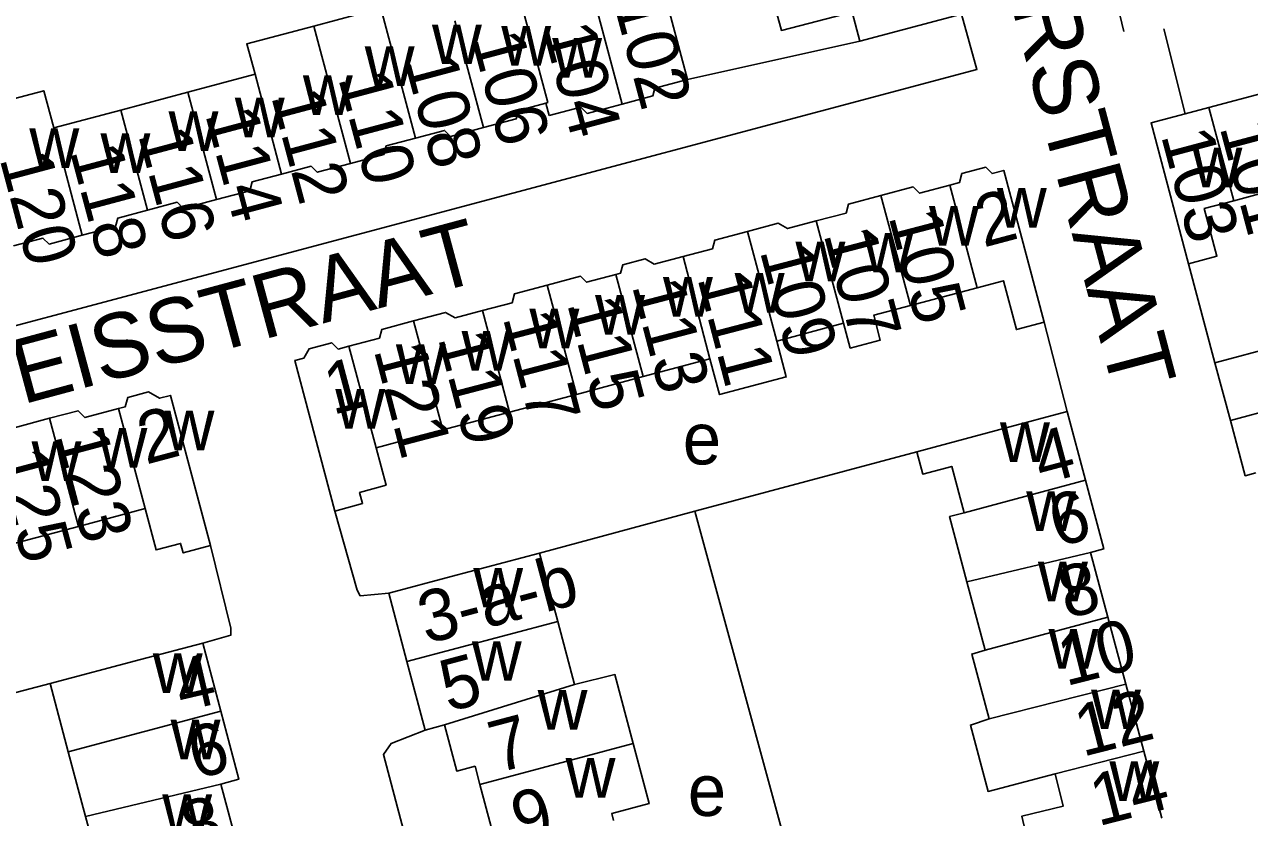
# Model space of a CAD drawing. Extents: x 161258 to 163262, y 380749 to 382054.
# Drawn here: x 162725.4 to 162820.5, y 381008.4 to 381069.9 of the extents above; entities that cross this region are included whole.
import ezdxf

# ---------------------------------------------------------------- set-up
doc = ezdxf.new("R2010")
doc.units = 0
for name, color, linetype in [('BLT_Basislijn', 7, 'Continuous'), ('BLT_Bebouwing', 7, 'Continuous'), ('BLT_Centroide', 7, 'Continuous'), ('BLT_Huisnummer', 7, 'Continuous'), ('BLT_Huisnummer_ tussenligend', 7, 'Continuous'), ('BLT_Huisnummer_reeks', 7, 'Continuous'), ('BLT_Onderverdeling_panden', 7, 'Continuous'), ('BLT_Straatnaam', 7, 'Continuous')]:
    doc.layers.add(name, color=color, linetype=linetype)

msp = doc.modelspace()

# ---------------------------------------------------------------- linework, layer by layer
at = {"layer": 'BLT_Basislijn'}
for p, q in [((162810.726, 381069.348), (162809.642, 381073.81)), ((162813.831, 381069.574), (162815.478, 381062.977)), ((162776.867, 381065.641), (162790.25, 381068.607)), ((162815.742, 381051.349), (162817.787, 381043.662)), ((162804.535, 381046.81), (162806.315, 381039.883)), ((162777.445, 381032.148), (162794.663, 381036.768)), ((162765.392, 381028.911), (162777.445, 381032.148)), ((162727.427, 381018.777), (162713.306, 381015.167))]:
    msp.add_line(p, q, dxfattribs=at)
for points in [[(162606.783, 381015.115), (162799.33, 381066.419), (162798.133, 381070.7)], [(162753.691, 381025.795), (162751.479, 381025.578), (162751.237, 381026.024), (162749.506, 381032.166)], [(162788.928, 380990.08), (162788.717, 380990.854), (162777.445, 381032.148)], [(162739.263, 381021.926), (162741.431, 381022.538), (162741.431, 381023.08), (162739.873, 381029.488)], [(162756.517, 381015.182), (162753.876, 381014.148), (162753.283, 381013.278), (162761.181, 380983.447), (162761.294, 380983.046)]]:
    msp.add_lwpolyline(points, dxfattribs=at)
at = {"layer": 'BLT_Bebouwing'}
for p, q in [((162790.25, 381068.607), (162798.133, 381070.7)), ((162743.316, 381066.047), (162738.103, 381064.657)), ((162738.103, 381064.657), (162732.895, 381063.268)), ((162821.803, 381064.659), (162817.32, 381063.467)), ((162766.136, 381062.838), (162765.878, 381063.804)), ((162817.32, 381063.467), (162815.478, 381062.977)), ((162732.895, 381063.268), (162727.696, 381061.881)), ((162799.344, 381049.481), (162794.163, 381048.104)), ((162788.98, 381046.725), (162783.799, 381045.347)), ((162778.613, 381043.967), (162773.434, 381042.59)), ((162818.985, 381039.2), (162817.787, 381043.662)), ((162773.434, 381042.59), (162768.253, 381041.211)), ((162768.253, 381041.211), (162763.07, 381039.833)), ((162763.07, 381039.833), (162757.889, 381038.455)), ((162807.74, 381034.553), (162806.315, 381039.883)), ((162757.889, 381038.455), (162752.708, 381037.077)), ((162734.791, 381032.356), (162729.609, 381030.972)), ((162729.609, 381030.972), (162724.422, 381029.587)), ((162765.392, 381028.911), (162766.805, 381023.604)), ((162809.486, 381023.945), (162808.147, 381028.951)), ((162753.691, 381025.795), (162755.104, 381020.488)), ((162766.805, 381023.604), (162768.114, 381018.704)), ((162810.877, 381018.741), (162809.486, 381023.945)), ((162740.667, 381016.647), (162739.263, 381021.926)), ((162755.104, 381020.488), (162756.517, 381015.182)), ((162812.268, 381013.538), (162810.877, 381018.741)), ((162756.517, 381015.182), (162758.011, 381015.58)), ((162728.832, 381013.501), (162730.172, 381008.47)), ((162813.66, 381008.334), (162812.268, 381013.538)), ((162741.895, 381006.359), (162740.662, 381010.993)), ((162760.77, 381010.962), (162762.153, 381005.771))]:
    msp.add_line(p, q, dxfattribs=at)
for points in [[(162776.867, 381065.641), (162775.579, 381070.473), (162773.82, 381077.07)], [(162753.072, 381071.166), (162747.881, 381069.782)], [(162783.526, 381071.816), (162784.155, 381069.446), (162789.654, 381070.857), (162790.25, 381068.607)], [(162747.881, 381069.782), (162742.676, 381068.394), (162743.316, 381066.047)], [(162771.805, 381063.723), (162774.182, 381064.357), (162774.346, 381064.969), (162776.867, 381065.641)], [(162727.696, 381061.881), (162726.92, 381064.763), (162721.715, 381063.375), (162722.506, 381060.497)], [(162761.033, 381061.903), (162763.577, 381062.582), (162763.754, 381063.237), (162765.878, 381063.804)], [(162766.136, 381062.838), (162768.598, 381063.494), (162769.091, 381063), (162771.805, 381063.723)], [(162815.478, 381062.977), (162812.836, 381062.274), (162815.742, 381051.349)], [(162755.762, 381061.086), (162758.026, 381061.69), (162758.49, 381061.225), (162761.033, 381061.903)], [(162750.733, 381059.134), (162753.321, 381059.824), (162753.498, 381060.482), (162755.762, 381061.086)], [(162745.383, 381058.302), (162747.676, 381058.914), (162748.145, 381058.444), (162750.733, 381059.134)], [(162804.535, 381046.81), (162801.405, 381058.58), (162800.504, 381058.341), (162800.018, 381058.829), (162798.163, 381058.335), (162797.974, 381057.636), (162797.213, 381057.434)], [(162740.326, 381056.322), (162742.907, 381057.011), (162743.09, 381057.69), (162745.383, 381058.302)], [(162797.213, 381057.434), (162794.859, 381056.808), (162794.367, 381057.302), (162791.876, 381056.639)], [(162824.717, 381053.705), (162822.514, 381053.119), (162821.524, 381056.84), (162819.244, 381056.233)], [(162734.966, 381055.505), (162737.264, 381056.118), (162737.746, 381055.634), (162740.326, 381056.322)], [(162791.876, 381056.639), (162789.36, 381055.97), (162789.174, 381055.281), (162786.853, 381054.663)], [(162815.742, 381051.349), (162817.947, 381051.936), (162816.965, 381055.627), (162819.244, 381056.233)], [(162729.917, 381053.552), (162732.493, 381054.239), (162732.669, 381054.892), (162734.966, 381055.505)], [(162781.519, 381053.854), (162778.979, 381053.178), (162778.8, 381052.514), (162776.538, 381051.912)], [(162786.853, 381054.663), (162784.629, 381054.072), (162783.91, 381054.49), (162781.519, 381053.854)], [(162724.576, 381052.732), (162726.864, 381053.342), (162727.341, 381052.865), (162729.917, 381053.552)], [(162776.538, 381051.912), (162774.292, 381051.315), (162773.579, 381051.728), (162771.841, 381051.266), (162771.664, 381050.61), (162771.311, 381050.516)], [(162771.311, 381050.516), (162769.04, 381049.912), (162768.58, 381050.373), (162765.984, 381049.682)], [(162765.984, 381049.682), (162763.442, 381049.006), (162763.256, 381048.318), (162760.961, 381047.708)], [(162804.535, 381046.81), (162802.384, 381046.237), (162801.377, 381050.022), (162799.344, 381049.481)], [(162760.961, 381047.708), (162758.836, 381047.143), (162758.097, 381047.572), (162755.623, 381046.913)], [(162794.163, 381048.104), (162791.316, 381047.346), (162791.828, 381045.42), (162789.492, 381044.799), (162788.98, 381046.725)], [(162755.623, 381046.913), (162753.144, 381046.254), (162752.962, 381045.582), (162750.598, 381044.954)], [(162817.787, 381043.662), (162822.616, 381044.959), (162830.489, 381047.075)], [(162783.799, 381045.347), (162784.536, 381042.573), (162779.354, 381041.194), (162778.613, 381043.967)], [(162750.598, 381044.954), (162749.76, 381044.731), (162749.276, 381045.217), (162747.511, 381044.747), (162747.095, 381044.03), (162746.399, 381043.845), (162749.506, 381032.166)], [(162739.873, 381029.488), (162736.762, 381041.139), (162735.918, 381040.913), (162735.061, 381041.409), (162733.439, 381040.976), (162733.244, 381040.253), (162732.729, 381040.115)], [(162732.729, 381040.115), (162730.122, 381039.419), (162729.593, 381039.949), (162727.381, 381039.358)], [(162794.663, 381036.768), (162801.485, 381038.592), (162806.315, 381039.883)], [(162727.381, 381039.358), (162724.638, 381038.626), (162724.436, 381037.875), (162722.366, 381037.322)], [(162820.971, 381035.127), (162820.14, 381034.904), (162818.985, 381039.2)], [(162749.506, 381032.166), (162751.668, 381032.74), (162751.435, 381033.616), (162753.488, 381034.166), (162752.708, 381037.077)], [(162798.325, 381032.038), (162797.365, 381035.632), (162795.127, 381035.034), (162794.663, 381036.768)], [(162808.147, 381028.951), (162809.165, 381029.223), (162807.74, 381034.553)], [(162739.873, 381029.488), (162737.743, 381028.919), (162737.547, 381029.652), (162735.644, 381029.147), (162734.791, 381032.356)], [(162798.554, 381026.681), (162797.202, 381031.738), (162798.325, 381032.038)], [(162765.392, 381028.911), (162758.523, 381027.082), (162753.691, 381025.795)], [(162799.976, 381021.363), (162798.554, 381026.681)], [(162739.263, 381021.926), (162734.432, 381020.641), (162727.427, 381018.777)], [(162800.262, 381016.038), (162798.917, 381021.069), (162799.976, 381021.363)], [(162727.427, 381018.777), (162728.832, 381013.501)], [(162768.114, 381018.704), (162771.235, 381019.487), (162772.661, 381014.131)], [(162740.662, 381010.993), (162742.071, 381011.368), (162740.667, 381016.647)], [(162805.403, 381011.79), (162800.196, 381010.419), (162798.819, 381015.56), (162800.262, 381016.038)], [(162758.011, 381015.58), (162758.966, 381011.993), (162760.394, 381012.373), (162760.77, 381010.962)], [(162772.661, 381014.131), (162773.9, 381009.48), (162770.994, 381008.706), (162771.138, 381008.166)], [(162806.663, 381006.552), (162803.441, 381005.833), (162802.801, 381008.495), (162806.01, 381009.267), (162805.403, 381011.79)], [(162730.172, 381008.47), (162731.592, 381003.227)]]:
    msp.add_lwpolyline(points, dxfattribs=at)
at = {"layer": 'BLT_Onderverdeling_panden'}
for p, q in [((162771.805, 381063.723), (162769.57, 381072.062)), ((162755.762, 381061.086), (162753.072, 381071.166)), ((162761.033, 381061.903), (162758.825, 381070.184)), ((162750.733, 381059.134), (162747.881, 381069.782)), ((162745.383, 381058.302), (162743.316, 381066.047)), ((162740.326, 381056.322), (162738.103, 381064.657)), ((162819.244, 381056.233), (162817.32, 381063.467)), ((162734.966, 381055.505), (162732.895, 381063.268)), ((162729.917, 381053.552), (162727.696, 381061.881)), ((162799.344, 381049.481), (162797.213, 381057.434)), ((162794.163, 381048.104), (162791.876, 381056.639)), ((162783.799, 381045.347), (162781.519, 381053.854)), ((162788.98, 381046.725), (162786.853, 381054.663)), ((162778.613, 381043.967), (162776.538, 381051.912)), ((162773.434, 381042.59), (162771.311, 381050.516)), ((162768.253, 381041.211), (162765.984, 381049.682)), ((162763.07, 381039.833), (162760.961, 381047.708)), ((162757.889, 381038.455), (162755.623, 381046.913)), ((162752.708, 381037.077), (162750.598, 381044.954)), ((162826.074, 381041.108), (162818.985, 381039.2)), ((162734.791, 381032.356), (162732.729, 381040.115)), ((162729.609, 381030.972), (162727.381, 381039.358)), ((162807.74, 381034.553), (162798.325, 381032.038)), ((162798.554, 381026.681), (162808.147, 381028.951)), ((162755.104, 381020.488), (162766.805, 381023.604)), ((162799.976, 381021.363), (162809.486, 381023.945)), ((162758.011, 381015.58), (162768.114, 381018.704)), ((162800.262, 381016.038), (162810.877, 381018.741)), ((162740.667, 381016.647), (162728.832, 381013.501)), ((162760.77, 381010.962), (162772.661, 381014.131)), ((162805.403, 381011.79), (162812.268, 381013.538)), ((162730.172, 381008.47), (162740.662, 381010.993))]:
    msp.add_line(p, q, dxfattribs=at)
msp.add_lwpolyline([(162765.878, 381063.804), (162766.025, 381063.843), (162764.217, 381070.59)], dxfattribs=at)

# ---------------------------------------------------------------- texts
at = {"layer": 'BLT_Centroide'}
for s, p in [('w', (162757.047, 381066.828)), ('w', (162762.422, 381066.719)), ('w', (162751.828, 381065.141)), ('w', (162766.374, 381065.784)), ('w', (162747.031, 381062.891)), ('w', (162741.75, 381061.156)), ('w', (162736.609, 381060.094)), ('w', (162725.812, 381058.766)), ('w', (162731.328, 381058.391)), ('w', (162816.047, 381057.281)), ('w', (162800.875, 381054.156)), ('w', (162795.609, 381052.75)), ('w', (162785.25, 381049.984)), ('w', (162790.516, 381050.672)), ('w', (162774.969, 381047.25)), ('w', (162780.531, 381047.547)), ('w', (162769.703, 381045.844)), ('w', (162764.609, 381044.781)), ('w', (162759.344, 381043.062)), ('w', (162754.25, 381042.016)), ('w', (162749.547, 381038.562)), ('w', (162736.297, 381036.875)), ('e', (162776.506, 381035.782)), ('w', (162801.117, 381035.969)), ('w', (162731.094, 381035.531)), ('w', (162725.984, 381034.5)), ('w', (162803.148, 381030.625)), ('w', (162804.062, 381025.156)), ('w', (162760.25, 381024.688)), ('w', (162804.883, 381019.938)), ('w', (162760.141, 381019)), ('w', (162735.391, 381018.062)), ('w', (162765.242, 381015.219)), ('w', (162808.18, 381015.25)), ('w', (162736.766, 381012.906)), ('w', (162767.414, 381009.938)), ('w', (162809.602, 381009.688)), ('e', (162776.895, 381008.517)), ('w', (162736.117, 381007.125))]:
    msp.add_text(s, height=4, dxfattribs=at).set_placement(p)
at = {"layer": 'BLT_Huisnummer'}
for s, height, rotation, p in [('102', 3.9999, 284.91757, (162771.089, 381071.693)), ('106', 4, 284.9411, (162760.096, 381068.838)), ('110', 3.9999, 284.94293, (162749.751, 381065.763)), ('114', 4, 284.93739, (162739.433, 381062.949)), ('103', 4, 284.89551, (162813.585, 381061.32)), ('118', 3.9999, 284.92683, (162728.937, 381060.096)), ('2', 4, 14.89471, (162799.832, 381052.594)), ('105', 4, 284.63997, (162792.449, 381055.03)), ('109', 4, 284.64525, (162782.464, 381052.358)), ('113', 4, 284.64074, (162772.542, 381049.664)), ('117', 4, 284.64452, (162762.524, 381047.177)), ('121', 4, 284.64256, (162752.513, 381044.672)), ('1', 4, 14.89471, (162749.333, 381039.604)), ('2', 4, 14.95035, (162734.842, 381035.756)), ('4', 4, 14.96555, (162804.336, 381034.21)), ('123', 3.9999, 284.92722, (162727.78, 381038.061)), ('8', 4, 14.28981, (162806.266, 381023.794)), ('4', 4, 13.04989, (162737.629, 381016.596)), ('12', 4, 14.28923, (162807.521, 381013.094)), ('7', 4, 14.80614, (162762.106, 381011.833)), ('8', 4, 14.90961, (162738.256, 381005.583))]:
    msp.add_text(s, height=height, rotation=rotation, dxfattribs=at).set_placement(p)
at = {"layer": 'BLT_Huisnummer_ tussenligend'}
for s, height, rotation, p in [('104', 3.9999, 284.91757, (162765.635, 381069.501)), ('108', 4, 284.9411, (162754.889, 381067.092)), ('112', 3.9999, 284.94293, (162744.547, 381064.358)), ('116', 4, 284.93739, (162734.225, 381061.384)), ('101', 4, 284.88901, (162818.135, 381061.957)), ('120', 3.9999, 284.92683, (162723.48, 381059.514)), ('107', 4, 284.63997, (162787.412, 381053.653)), ('111', 4, 284.64525, (162777.618, 381050.248)), ('115', 4, 284.64074, (162767.508, 381048.274)), ('119', 4, 284.64452, (162757.491, 381045.605)), ('125', 3.9999, 284.92722, (162723.093, 381036.496)), ('6', 4, 14.96555, (162805.551, 381029.345)), ('10', 3.9999, 14.28981, (162806.219, 381018.567)), ('5', 4, 14.91331, (162758.3, 381016.567)), ('6', 4, 13.04989, (162738.67, 381011.384)), ('14', 4, 14.28923, (162808.721, 381007.705)), ('9', 4, 14.80614, (162763.85, 381006.275))]:
    msp.add_text(s, height=height, rotation=rotation, dxfattribs=at).set_placement(p)
at = {"layer": 'BLT_Huisnummer_reeks'}
msp.add_text('3-a-b', height=4, rotation=14.91331, dxfattribs=at).set_placement((162756.607, 381021.835))
at = {"layer": 'BLT_Straatnaam'}
for s, rotation, p in [('LAURIERSTRAAT', 284.83079, (162795.821, 381094.672)), ('EDELWEISSTRAAT', 15.08488, (162702.299, 381034.228))]:
    msp.add_text(s, height=5, rotation=rotation, dxfattribs=at).set_placement(p)

doc.saveas('drawing.dxf')
